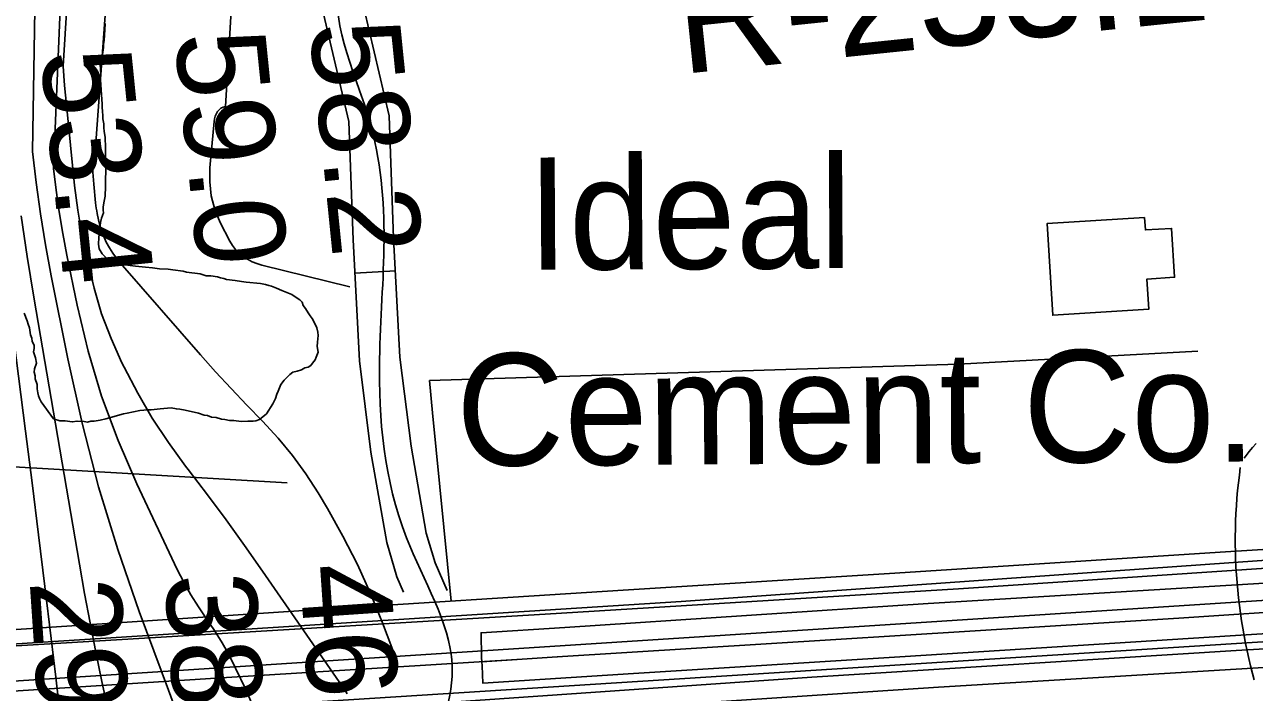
# Model space of a CAD drawing. Extents: x 3313442 to 3351311, y 721974 to 747360.
# Drawn here: x 3324727 to 3325637, y 729942 to 730435 of the extents above; entities that cross this region are included whole.
import ezdxf

# ---------------------------------------------------------------- set-up
doc = ezdxf.new("R2010")
doc.units = 0
for name, color, linetype in [('V-BLDG-IDEN', 7, 'Continuous'), ('V-BLDG-OTLN', 7, 'Continuous'), ('V-BRDG-OTLN', 7, 'Continuous'), ('V-RAIL-TRAK', 7, 'Continuous'), ('V-RIVR-RANG', 7, 'Continuous'), ('V-RIVR-RANG-IDEN', 7, 'Continuous'), ('V-ROAD-CNTR', 7, 'Continuous'), ('V-SITE-VEGE', 7, 'Continuous'), ('V-TOPO-MAJR', 7, 'Continuous'), ('V-TOPO-MINR', 7, 'Continuous'), ('V-TOPO-SHOR', 7, 'Continuous'), ('V-UTIL-LINE', 7, 'Continuous')]:
    doc.layers.add(name, color=color, linetype=linetype)

msp = doc.modelspace()

# ---------------------------------------------------------------- linework, layer by layer
at = {"layer": 'V-BLDG-OTLN'}
msp.add_lwpolyline([(3325555.84, 730292.79), (3325556.42, 730283.58), (3325575.8, 730284.78), (3325578.05, 730248.57), (3325557.55, 730247.3), (3325558.94, 730224.97), (3325487.84, 730220.56), (3325483.63, 730288.31)], close=True, dxfattribs=at)
at = {"layer": 'V-BRDG-OTLN'}
for points in [[(3325676.61, 729961.93), (3325403.23, 729945.42), (3325134.28, 729927.72), (3324948.68, 729916.36), (3324716.77, 729901.2), (3324586.68, 729892.87), (3324582.42, 729979.53), (3324713.54, 729987.61), (3324937.54, 730002.27), (3325170.02, 730017.23), (3325371.06, 730029.8), (3325611.64, 730045.26), (3325891.58, 730062.67)], [(3320027.11, 729673.66), (3320326.85, 729692.23), (3320625.72, 729712.54), (3321034.35, 729739.15), (3321378.17, 729762.12), (3321742.23, 729785.3), (3322315.22, 729820.18), (3322734.66, 729846.49), (3323163.18, 729876.19), (3323634.51, 729906.06), (3324271.4, 729946.09), (3324700.11, 729974.82), (3325112.37, 729999.31), (3325418.16, 730018.21), (3325686.56, 730036.07), (3325892.89, 730048.88)], [(3325669.09, 730023.71), (3325395.71, 730007.2), (3325126.76, 729989.49), (3325064.83, 729985.7), (3325065.16, 729967.35), (3325065.48, 729964.24), (3325065.69, 729961.15), (3325066.23, 729948.3), (3325177.54, 729955.46), (3325378.57, 729968.03), (3325619.16, 729983.49), (3325899.1, 730000.9)], [(3320029.11, 729613.8), (3320339.22, 729634.27), (3320661.41, 729653.97), (3320967.6, 729674.61), (3321254.1, 729691.76), (3321493.35, 729708.2), (3321721.78, 729722.63), (3322170.54, 729751.36), (3322654.03, 729782.08), (3323222.6, 729817.79), (3323823.97, 729856.26), (3324302.83, 729887.22), (3324624.44, 729907.32), (3324993.14, 729930.83), (3325309.56, 729952.91), (3325623.66, 729972.5), (3325900.26, 729988.64)]]:
    msp.add_lwpolyline(points, dxfattribs=at)
at = {"layer": 'V-RAIL-TRAK'}
msp.add_lwpolyline([(3327014.9, 730087.4), (3326695.15, 730068.27), (3326424.75, 730051.48), (3326190.98, 730035.2), (3325892.69, 730017.1), (3325581.29, 729996.5), (3325121.28, 729967.73), (3325095.26, 729966.1), (3325065.48, 729964.24), (3325095.26, 729966.1), (3325121.28, 729967.73), (3325095.26, 729966.1), (3324868.51, 729951.98), (3324656.38, 729938.47), (3324356.33, 729919.33), (3324042.5, 729898.58), (3323751.69, 729879.36), (3323461.24, 729861.36), (3323178.8, 729842.76), (3322934.75, 729827.11), (3322611.67, 729806.1)], dxfattribs=at)
at = {"layer": 'V-ROAD-CNTR'}
msp.add_line((3325001.43, 730253.3), (3324971.47, 730251.75), dxfattribs=at)
for points in [[(3324978.31, 730446.96), (3324996.87, 730367.89), (3325000.17, 730277.61), (3325004.72, 730189.45), (3325013.08, 730123.77), (3325024.35, 730059.25), (3325030.8, 730037.25), (3325039.69, 730016.91)], [(3324948.34, 730443.39), (3324967, 730363.87), (3324970.2, 730276.29), (3324974.81, 730186.78), (3324983.41, 730119.29), (3324995.09, 730052.43), (3325002.55, 730026.98), (3325007.48, 730015.7)], [(3321910.81, 729798.53), (3325212.97, 730008.78), (3325897.53, 730057.12), (3327426.35, 730145.26), (3327871.18, 730180.02)], [(3328093.02, 730163.12), (3327927.05, 730155.1), (3326543.39, 730067.78), (3321912.71, 729768.69)], [(3325638.33, 730125.6), (3325635.79, 730122.66), (3325633.31, 730119.67), (3325630.93, 730116.65), (3325629.6, 730114.9)], [(3325626.67, 730107.79), (3325625.94, 730102.26), (3325625.28, 730096.61), (3325624.7, 730090.95), (3325624.2, 730085.28), (3325623.79, 730079.61), (3325623.46, 730073.93), (3325623.21, 730068.25), (3325623.05, 730062.56), (3325622.96, 730056.87), (3325622.97, 730051.19), (3325623.05, 730045.5), (3325623.22, 730039.81), (3325623.47, 730034.13), (3325623.81, 730028.45), (3325624.22, 730022.78), (3325624.73, 730017.11), (3325625.31, 730011.46), (3325625.97, 730005.81), (3325626.72, 730000.17), (3325627.55, 729994.54), (3325628.47, 729988.93), (3325629.46, 729983.33), (3325630.54, 729977.74), (3325631.7, 729972.17), (3325632.94, 729966.62), (3325634.26, 729961.09), (3325635.66, 729955.58), (3325636.92, 729950.91)], [(3327244.32, 730080.97), (3325899.84, 729995.27), (3321914.87, 729742.58)]]:
    msp.add_lwpolyline(points, dxfattribs=at)
msp.add_spline([(3326478.04, 730210.35), (3326482.35, 730403.29), (3326476.58, 730549.39), (3326473.61, 730637.71), (3326464.08, 730712.16), (3326370.96, 730713.71), (3326297.71, 730698.23), (3326169.71, 730725.9), (3326116.45, 730727.88), (3325982.64, 730689.67), (3325835.77, 730656.61), (3325666.24, 730661.4), (3325490.23, 730637.83), (3325403.5, 730634.84), (3325340.74, 730586.21), (3325201.43, 730523.99), (3325133.39, 730524.77), (3325012.9, 730513.46), (3324963.14, 730471.34), (3324981.93, 730365.88), (3324989.76, 730188.11), (3325009.72, 730055.84), (3325043.42, 729962.4), (3324997.98, 729812.51), (3325023.28, 729696.25), (3325064.51, 729608.4), (3325131.37, 729516.61), (3325150.36, 729377.77), (3325146.87, 729245.63), (3325126.45, 729132.53), (3325181.34, 729069.88), (3325338.87, 729062.31), (3325343.56, 728961.08), (3325372.85, 728878.06), (3325434.63, 728797.89), (3325537.34, 728748.77), (3325622.45, 728705.03), (3325714.6, 728675.45), (3325802.67, 728663.42), (3325976.26, 728695.07), (3326194.29, 728726.31), (3326466.63, 728765.32), (3326625.11, 728781.99), (3326781.78, 728849.74), (3326900.23, 728862.4), (3326981.75, 728872.83), (3327122.94, 728906.43), (3327349.99, 728934.63), (3327499.05, 728974.33), (3327515.65, 728986.69), (3327498, 729057.12), (3327490.77, 729119.3), (3327510.96, 729180.47), (3327588.76, 729283.84), (3327686.92, 729357.21), (3327753.03, 729377.43), (3327803.43, 729380.44), (3327847.87, 729388.87), (3327934.83, 729389.79), (3328039.14, 729390.23), (3328120.59, 729395.25), (3328249.21, 729403.96), (3328319.73, 729407.13), (3328384.24, 729401.49), (3328424.57, 729387.35), (3328470.08, 729368.59), (3328549.26, 729327.46), (3328661.09, 729275.68), (3328877.57, 729175.26), (3328980.19, 729125.77), (3329049.22, 729101.24), (3329067.8, 729104.63), (3329088.99, 729118.36), (3329113.61, 729147.02), (3329153.45, 729227.36), (3329182.49, 729301.19), (3329201.64, 729378.5), (3329199.66, 729471.18), (3329192.73, 729551.54), (3329166.92, 729646.66), (3329121.79, 729727.55), (3329091.49, 729778.71), (3329016.19, 729835.66), (3328941.73, 729880.13), (3328875.38, 729924.2), (3328789.67, 729967.9), (3328700.81, 730000.01), (3328643.56, 730009.51), (3328577.01, 730014.29), (3328435.19, 729993.91), (3328288.99, 729968.49), (3328169.46, 729944.48), (3328087.81, 729917.23), (3328042.9, 729880.41), (3327999.54, 729814.48), (3327967.22, 729727.08), (3328009.37, 729621.12)], degree=3, dxfattribs=at)
at = {"layer": 'V-SITE-VEGE'}
for points in [[(3324786.79, 730436.34), (3324786.39, 730431.73), (3324785.96, 730423.92), (3324785.58, 730420.73), (3324785.56, 730418.6), (3324784.79, 730413.29), (3324783.7, 730409.75), (3324782.95, 730406.2), (3324783.59, 730398.74), (3324783.22, 730396.62), (3324783.2, 730394.49), (3324784.45, 730376.73), (3324784.43, 730374.6), (3324784.75, 730371.05), (3324785.08, 730368.56), (3324785.06, 730365.72), (3324785.73, 730362.16), (3324785.71, 730359.32), (3324786.03, 730356.48), (3324786.7, 730352.21), (3324786.98, 730344.4), (3324786.9, 730335.17), (3324787.23, 730332.33), (3324787.07, 730315.65), (3324786.65, 730308.55), (3324785.9, 730305.01), (3324785.15, 730300.76), (3324785.13, 730298.28), (3324785.46, 730296.14), (3324784.01, 730292.25), (3324783.27, 730289.06)], [(3324783.27, 730289.06), (3324782.1, 730278.07), (3324781.7, 730273.1), (3324782.37, 730269.55), (3324784.47, 730265.98), (3324788.69, 730261.68), (3324790.8, 730260.24), (3324794.35, 730259.5), (3324799.66, 730258.03), (3324809.23, 730256.87), (3324816.68, 730256.09), (3324821.64, 730255.69), (3324826.96, 730254.93), (3324833.35, 730254.51), (3324836.89, 730254.12), (3324844.33, 730252.99), (3324846.81, 730252.26), (3324857.1, 730251.09), (3324861.34, 730249.64), (3324864.89, 730249.6), (3324869.85, 730248.84), (3324871.98, 730248.11), (3324874.46, 730247.73), (3324876.58, 730247.01), (3324882.96, 730246.23), (3324887.57, 730245.48), (3324891.12, 730245.09), (3324901.75, 730243.93), (3324905.3, 730243.18), (3324907.77, 730242.45), (3324909.9, 730242.08), (3324913.44, 730240.62), (3324917.33, 730238.81), (3324924.75, 730235.9), (3324927.22, 730234.1), (3324930.75, 730231.94), (3324932.51, 730230.15), (3324933.19, 730227.66), (3324934.95, 730225.51), (3324937.04, 730222.3), (3324938.45, 730220.15), (3324939.85, 730218.01), (3324941.94, 730214.44), (3324943.33, 730211.23), (3324944.01, 730208.03), (3324944.34, 730205.54), (3324943.94, 730200.58), (3324943.56, 730197.39), (3324944.23, 730193.12), (3324942.77, 730189.59), (3324942.04, 730187.46), (3324940.24, 730185), (3324938.81, 730183.23), (3324937.02, 730182.19), (3324934.53, 730181.5), (3324932.03, 730180.1), (3324928.83, 730179.07), (3324925.63, 730178.39), (3324923.48, 730176.63), (3324919.18, 730172.42), (3324916.67, 730169.24), (3324914.85, 730164.29), (3324913.76, 730162.17), (3324912.67, 730158.99), (3324910.85, 730155.1), (3324906.17, 730147.69), (3324900.81, 730143.48), (3324898.31, 730142.44), (3324896.18, 730142.1), (3324892.28, 730142.14), (3324887.3, 730141.83), (3324881.98, 730142.59), (3324878.79, 730142.62), (3324875.25, 730143.37), (3324872.77, 730143.74), (3324868.87, 730144.85), (3324865.33, 730145.24), (3324862.5, 730146.33), (3324860.02, 730146.71), (3324855.77, 730148.17), (3324845.85, 730150.39), (3324841.95, 730151.14), (3324839.47, 730151.16), (3324835.57, 730151.91), (3324827.4, 730151.27), (3324820.65, 730150.63), (3324818.17, 730150.65), (3324812.48, 730150), (3324802.88, 730147.96), (3324800.39, 730147.62), (3324787.22, 730143.84), (3324782.95, 730142.82), (3324778.69, 730142.15), (3324776.2, 730142.17), (3324773.71, 730141.49), (3324771.23, 730141.86), (3324765.91, 730142.27), (3324762.35, 730141.59), (3324757.03, 730142.35), (3324753.13, 730142.39), (3324748.53, 730143.86)], [(3324748.53, 730143.86), (3324739.42, 730156.36), (3324738.02, 730158.86), (3324737.33, 730161), (3324737, 730163.13), (3324736.31, 730165.98), (3324736.35, 730169.17), (3324734.96, 730173.45), (3324734.98, 730175.57), (3324734.3, 730178.42), (3324734.33, 730180.9), (3324735.79, 730185.15), (3324735.11, 730189.06), (3324733.73, 730193.33), (3324734.11, 730195.82), (3324734.14, 730198.3), (3324732.74, 730201.15), (3324732.41, 730203.64), (3324731.37, 730206.14), (3324730.71, 730211.11), (3324729.67, 730213.96), (3324728.98, 730216.45), (3324726.91, 730222.15)]]:
    msp.add_lwpolyline(points, dxfattribs=at)
at = {"layer": 'V-TOPO-MAJR'}
for points in [[(3325003.09, 729963.73), (3324992, 729992.91), (3324983.07, 730014.69), (3324973.4, 730036.13), (3324962.63, 730057.03), (3324951.12, 730077.57), (3324944.23, 730089.15), (3324935.12, 730103.26), (3324925.36, 730116.86), (3324914.62, 730129.7), (3324903.23, 730142.04), (3324891.46, 730154.1), (3324879.85, 730166.31), (3324868.48, 730178.74), (3324857.26, 730191.32), (3324797.87, 730259.2), (3324794.99, 730262.75), (3324792.3, 730266.43), (3324789.9, 730270.31), (3324787.52, 730274.67), (3324785.71, 730278.65), (3324784.12, 730282.71), (3324782.86, 730286.88), (3324781.81, 730291.12), (3324780.87, 730295.76), (3324780.49, 730297.75), (3324780.16, 730299.75), (3324779.64, 730303.77), (3324778.25, 730317.38), (3324777.99, 730320.4), (3324777.79, 730323.43), (3324777.69, 730326.46), (3324777.65, 730329.49), (3324777.79, 730332.5), (3324778.09, 730335.49), (3324778.66, 730338.45), (3324779.39, 730341.38), (3324859.13, 731432.4)], [(3324752.91, 729928.83), (3324750.11, 729952.8), (3324746.68, 729981.52), (3324742.05, 730019.84), (3324737.37, 730058.15), (3324732.62, 730096.45), (3324727.81, 730134.74), (3324717.49, 730216.24)]]:
    msp.add_lwpolyline(points, dxfattribs=at)
at = {"layer": 'V-TOPO-MINR'}
for points in [[(3324967.65, 730241.44), (3324902.63, 730257.56), (3324898.95, 730258.7), (3324895.38, 730260.09), (3324892, 730261.88), (3324888.72, 730263.92), (3324885.77, 730266.35), (3324883.09, 730269.02), (3324880.83, 730272.06), (3324878.85, 730275.34), (3324871.9, 730289.08), (3324867.97, 730298.83), (3324865.18, 730308.81), (3324864.11, 730319.1), (3324864.18, 730329.62), (3324867.36, 730363.9), (3324867.68, 730365.81), (3324868.17, 730367.67), (3324869.82, 730371.14), (3324872.4, 730373.68), (3324874.03, 730374.4), (3324875.83, 730374.84), (3324939.24, 731442.44)], [(3324965.9, 729940.58), (3324964.31, 729943.03), (3324903.24, 730031.19), (3324889.83, 730050.23), (3324876.23, 730069.11), (3324862.33, 730087.78), (3324848.23, 730106.31), (3324846.2, 730108.93), (3324833.53, 730126.39), (3324821.61, 730144.31), (3324810.81, 730162.93), (3324800.75, 730182.01), (3324799.11, 730185.37), (3324791.15, 730203.36), (3324784.13, 730221.67), (3324778.53, 730240.46), (3324773.86, 730259.57), (3324769.6, 730280.41), (3324767.91, 730289.36), (3324766.4, 730298.34), (3324765.16, 730307.36), (3324764.1, 730316.41), (3324758.01, 730376.06), (3324756.75, 730390.42), (3324755.75, 730404.79), (3324818.07, 731414.25)], [(3324897.13, 729928.68), (3324890.8, 729943.6), (3324883.25, 729959.54), (3324878.45, 729969), (3324873.31, 729978.26), (3324867.67, 729987.23), (3324861.69, 729995.99), (3324855.72, 730004.76), (3324850.07, 730013.72), (3324844.93, 730022.98), (3324840.12, 730032.44), (3324810.07, 730095.76), (3324796.23, 730127.89), (3324783.99, 730160.55), (3324774.15, 730194.01), (3324765.9, 730228.01), (3324758.34, 730265.06), (3324755.33, 730280.97), (3324752.65, 730296.94), (3324750.44, 730312.97), (3324748.56, 730329.06), (3324790.98, 731343.04)], [(3324839.72, 729926.5), (3324833.69, 729943.07), (3324812, 730001.32), (3324796.14, 730047.29), (3324781.77, 730093.69), (3324769.65, 730140.73), (3324759.03, 730188.19), (3324746.82, 730249.66), (3324742.61, 730272.56), (3324738.83, 730295.52), (3324735.71, 730318.58), (3324733.01, 730341.7), (3324747.05, 731197.2)], [(3324789.15, 729926.96), (3324784.32, 729949.57), (3324779.83, 729971.23), (3324775.53, 729992.91), (3324771.49, 730014.65), (3324767.63, 730036.43), (3324733.88, 730234), (3324729.06, 730263.99), (3324724.66, 730294.04)]]:
    msp.add_lwpolyline(points, dxfattribs=at)
at = {"layer": 'V-TOPO-SHOR'}
msp.add_lwpolyline([(3325042.77, 730008.98), (3325028.92, 730148.42), (3325026.73, 730172.15), (3325418.08, 730184.38), (3325595.24, 730194.05)], dxfattribs=at)
at = {"layer": 'V-UTIL-LINE'}
msp.add_line((3322095.44, 730260.93), (3324921.38, 730096.6), dxfattribs=at)

# ---------------------------------------------------------------- texts
at = {"layer": 'V-BLDG-IDEN'}
for s, p in [('Ideal', (3325099.19, 730254.1)), ('Cement Co.', (3325046.54, 730109.11))]:
    msp.add_text(s, height=83, rotation=0.31789, dxfattribs=at).set_placement(p)
at = {"layer": 'V-RIVR-RANG'}
for s, rotation, p in [('59.0', 275.76833, (3324838.01, 730428.07)), ('58.2', 275.76833, (3324937.77, 730435.47)), ('53.4', 275.76833, (3324738.83, 730414.88)), ('38.3', 273.89833, (3324830.76, 730028.02)), ('46.5', 273.89833, (3324930.51, 730035.06)), ('29.0', 273.89833, (3324730.81, 730023.88))]:
    msp.add_text(s, height=67, rotation=rotation, dxfattribs=at).set_placement(p)
at = {"layer": 'V-RIVR-RANG-IDEN'}
msp.add_text('R-233.1', height=83, rotation=5.90872, dxfattribs=at).set_placement((3325212.9, 730398.85))

doc.saveas('drawing.dxf')
